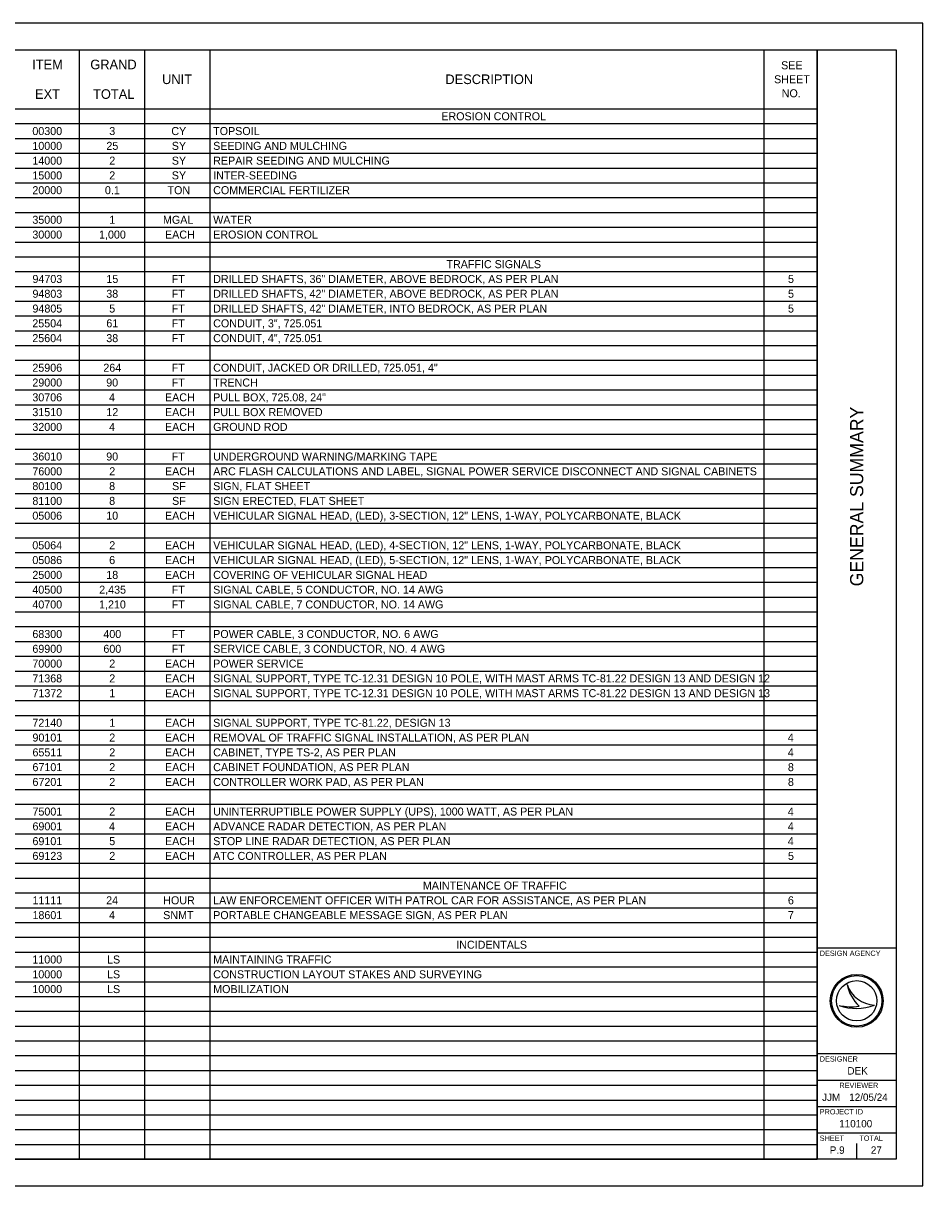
# Model space of a CAD drawing. Extents: x 0 to 34, y 0 to 22.
# Drawn here: x 16.98 to 34, y 0 to 22 of the extents above; entities that cross this region are included whole.
import ezdxf

# ---------------------------------------------------------------- set-up
doc = ezdxf.new("R2010")
doc.units = 0
for name, color, linetype in [('Default', 7, 'Continuous'), ('SH_Border', 7, 'Continuous'), ('SH_Cut_Line', 7, 'Continuous'), ('SH_Data', 7, 'Continuous')]:
    doc.layers.add(name, color=color, linetype=linetype)

msp = doc.modelspace()

# ---------------------------------------------------------------- linework, layer by layer
at = {"layer": 'Default'}
for p, q in [((1.5, 21.5), (32, 21.5)), ((18.035, 21.5), (18.035, 0.502)), ((19.27, 21.5), (19.27, 0.502)), ((20.505, 21.5), (20.505, 0.502)), ((30.995, 21.5), (30.995, 0.502)), ((32, 21.5), (32, 0.502)), ((1.5, 20.38), (32, 20.38)), ((1.5, 20.1), (32, 20.1)), ((1.5, 19.82), (32, 19.82)), ((1.5, 19.54), (32, 19.54)), ((1.5, 19.26), (32, 19.26)), ((1.5, 18.98), (32, 18.98)), ((1.5, 18.7), (32, 18.7)), ((1.5, 18.42), (32, 18.42)), ((1.5, 18.14), (32, 18.14)), ((1.5, 17.86), (32, 17.86)), ((1.5, 17.58), (32, 17.58)), ((1.5, 17.3), (32, 17.3)), ((1.5, 17.021), (32, 17.021)), ((1.5, 16.741), (32, 16.741)), ((1.5, 16.461), (32, 16.461)), ((1.5, 16.181), (32, 16.181)), ((1.5, 15.901), (32, 15.901)), ((1.5, 15.621), (32, 15.621)), ((1.5, 15.341), (32, 15.341)), ((1.5, 15.061), (32, 15.061)), ((1.5, 14.781), (32, 14.781)), ((1.5, 14.501), (32, 14.501)), ((1.5, 14.221), (32, 14.221)), ((1.5, 13.941), (32, 13.941)), ((1.5, 13.661), (32, 13.661)), ((1.5, 13.381), (32, 13.381)), ((1.5, 13.101), (32, 13.101)), ((1.5, 12.821), (32, 12.821)), ((1.5, 12.541), (32, 12.541)), ((1.5, 12.261), (32, 12.261)), ((1.5, 11.981), (32, 11.981)), ((1.5, 11.701), (32, 11.701)), ((1.5, 11.421), (32, 11.421)), ((1.5, 11.141), (32, 11.141)), ((1.5, 10.861), (32, 10.861)), ((1.5, 10.581), (32, 10.581)), ((1.5, 10.301), (32, 10.301)), ((1.5, 10.021), (32, 10.021)), ((1.5, 9.741), (32, 9.741)), ((1.5, 9.461), (32, 9.461)), ((1.5, 9.181), (32, 9.181)), ((1.5, 8.901), (32, 8.901)), ((1.5, 8.621), (32, 8.621)), ((1.5, 8.342), (32, 8.342)), ((1.5, 8.062), (32, 8.062)), ((1.5, 7.782), (32, 7.782)), ((1.5, 7.502), (32, 7.502)), ((1.5, 7.222), (32, 7.222)), ((1.5, 6.942), (32, 6.942)), ((1.5, 6.662), (32, 6.662)), ((1.5, 6.382), (32, 6.382)), ((1.5, 6.102), (32, 6.102)), ((1.5, 5.822), (32, 5.822)), ((1.5, 5.542), (32, 5.542)), ((1.5, 5.262), (32, 5.262)), ((1.5, 4.982), (32, 4.982)), ((1.5, 4.702), (32, 4.702)), ((1.5, 4.422), (32, 4.422)), ((1.5, 4.142), (32, 4.142)), ((1.5, 3.862), (32, 3.862)), ((1.5, 3.582), (32, 3.582)), ((1.5, 3.302), (32, 3.302)), ((1.5, 3.022), (32, 3.022)), ((1.5, 2.742), (32, 2.742)), ((1.5, 2.462), (32, 2.462)), ((1.5, 2.182), (32, 2.182)), ((1.5, 1.902), (32, 1.902)), ((1.5, 1.622), (32, 1.622)), ((1.5, 1.342), (32, 1.342)), ((1.5, 1.062), (32, 1.062)), ((1.5, 0.782), (32, 0.782)), ((1.5, 0.502), (32, 0.502))]:
    msp.add_line(p, q, dxfattribs=at)
at = {"layer": 'SH_Border'}
for p, q in [((32, 0.5), (32, 21.5)), ((32, 4.5), (33.5, 4.5)), ((32, 2.5), (33.5, 2.5)), ((32, 2), (33.5, 2)), ((32, 1.5), (33.5, 1.5)), ((32, 1), (33.5, 1))]:
    msp.add_line(p, q, dxfattribs=at)
msp.add_lwpolyline([(1.5, 21.5), (33.5, 21.5), (33.5, 0.5), (1.5, 0.5)], close=True, dxfattribs=at)
at = {"layer": 'SH_Cut_Line'}
msp.add_lwpolyline([(0, 0), (34, 0), (34, 22), (0, 22)], close=True, dxfattribs=at)
at = {"layer": 'SH_Data'}
for p, q in [((32.567, 3.81), (32.567, 3.81)), ((32.417, 3.41), (32.417, 3.41)), ((32.75, 3.5), (32.75, 3.5)), ((33.087, 3.419), (33.087, 3.419)), ((32.375, 0.675), (32.375, 0.675)), ((32.75, 0.5), (32.75, 0.8))]:
    msp.add_line(p, q, dxfattribs=at)
for radius in [0.5, 0.477, 0.477, 0.382]:
    msp.add_circle((32.75, 3.5), radius, dxfattribs=at)
for centre, radius, start, end in [((33.116, 3.998), 0.58, 198.9257, 198.9319), ((33.347, 3.97), 0.796, 191.6379, 191.6421), ((33.116, 3.998), 0.58, 198.9319, 267.1657), ((33.347, 3.97), 0.796, 191.6421, 226.0947), ((32.739, 4.37), 1.013, 251.4576, 290.0832), ((32.648, 4.654), 1.266, 259.4964, 259.4995), ((32.739, 4.37), 1.013, 251.4527, 251.4576), ((32.648, 4.654), 1.266, 259.4995, 276.6672)]:
    msp.add_arc(centre, radius, start, end, dxfattribs=at)

# ---------------------------------------------------------------- texts
at = {"layer": 'Default'}
for s, height, p in [('ITEM', 0.1818, (17.145, 21.129)), ('GRAND', 0.1818, (18.245, 21.129)), ('SEE ', 0.1515, (31.32, 21.129)), ('UNIT', 0.1818, (19.604, 20.849)), ('DESCRIPTION', 0.18181, (24.965, 20.849)), ('SHEET ', 0.1515, (31.187, 20.864)), ('EXT', 0.1818, (17.199, 20.569)), ('TOTAL', 0.1818, (18.297, 20.569)), ('NO.', 0.1515, (31.331, 20.599)), ('EROSION CONTROL', 0.15151, (24.889, 20.164)), ('00300', 0.1515, (17.149, 19.884)), ('3', 0.152, (18.604, 19.884)), ('CY', 0.1515, (19.779, 19.884)), ('TOPSOIL', 0.1515, (20.571, 19.884)), ('10000', 0.1515, (17.149, 19.604)), ('25', 0.1515, (18.55, 19.604)), ('SY', 0.1515, (19.788, 19.604)), ('SEEDING AND MULCHING', 0.15151, (20.571, 19.604)), ('14000', 0.1515, (17.149, 19.324)), ('2', 0.152, (18.604, 19.324)), ('SY', 0.1515, (19.788, 19.324)), ('REPAIR SEEDING AND MULCHING', 0.15151, (20.571, 19.324)), ('15000', 0.1515, (17.149, 19.045)), ('2', 0.152, (18.604, 19.045)), ('SY', 0.1515, (19.788, 19.045)), ('INTER-SEEDING', 0.15151, (20.571, 19.045)), ('20000', 0.1515, (17.149, 18.765)), ('0.1', 0.1515, (18.522, 18.765)), ('TON', 0.1515, (19.707, 18.765)), ('COMMERCIAL FERTILIZER', 0.15151, (20.571, 18.765)), ('35000', 0.1515, (17.149, 18.205)), ('1', 0.152, (18.604, 18.205)), ('MGAL', 0.1515, (19.621, 18.205)), ('WATER', 0.1515, (20.571, 18.205)), ('30000', 0.1515, (17.149, 17.925)), ('1,000', 0.1515, (18.411, 17.925)), ('EACH', 0.1515, (19.659, 17.925)), ('EROSION CONTROL', 0.15151, (20.571, 17.925)), ('TRAFFIC SIGNALS', 0.15151, (24.986, 17.365)), ('94703', 0.1515, (17.151, 17.085)), ('15', 0.1515, (18.55, 17.085)), ('FT', 0.1515, (19.786, 17.085)), ('DRILLED SHAFTS, 36" DIAMETER, ABOVE BEDROCK, AS PER PLAN', 0.15151, (20.571, 17.085)), ('5', 0.152, (31.45, 17.085)), ('94803', 0.1515, (17.151, 16.805)), ('38', 0.1515, (18.548, 16.805)), ('FT', 0.1515, (19.786, 16.805)), ('DRILLED SHAFTS, 42" DIAMETER, ABOVE BEDROCK, AS PER PLAN', 0.15151, (20.571, 16.805)), ('5', 0.152, (31.45, 16.805)), ('94805', 0.1515, (17.151, 16.525)), ('5', 0.152, (18.604, 16.525)), ('FT', 0.1515, (19.786, 16.525)), ('DRILLED SHAFTS, 42" DIAMETER, INTO BEDROCK, AS PER PLAN', 0.15151, (20.571, 16.525)), ('5', 0.152, (31.45, 16.525)), ('25504', 0.1515, (17.148, 16.245)), ('61', 0.1515, (18.549, 16.245)), ('FT', 0.1515, (19.786, 16.245)), ('CONDUIT, 3", 725.051', 0.15151, (20.571, 16.245)), ('25604', 0.1515, (17.148, 15.965)), ('38', 0.1515, (18.548, 15.965)), ('FT', 0.1515, (19.786, 15.965)), ('CONDUIT, 4", 725.051', 0.15151, (20.571, 15.965)), ('25906', 0.1515, (17.149, 15.405)), ('264', 0.1515, (18.492, 15.405)), ('FT', 0.1515, (19.786, 15.405)), ('CONDUIT, JACKED OR DRILLED, 725.051, 4"', 0.15151, (20.571, 15.405)), ('29000', 0.1515, (17.149, 15.125)), ('90', 0.1515, (18.547, 15.125)), ('FT', 0.1515, (19.786, 15.125)), ('TRENCH', 0.1515, (20.571, 15.125)), ('30706', 0.1515, (17.149, 14.845)), ('4', 0.152, (18.601, 14.845)), ('EACH', 0.1515, (19.659, 14.845)), ('PULL BOX, 725.08, 24"', 0.15151, (20.571, 14.845)), ('31510', 0.1515, (17.149, 14.565)), ('12', 0.1515, (18.549, 14.565)), ('EACH', 0.1515, (19.659, 14.565)), ('PULL BOX REMOVED', 0.15151, (20.571, 14.565)), ('32000', 0.1515, (17.149, 14.285)), ('4', 0.152, (18.601, 14.285)), ('EACH', 0.1515, (19.659, 14.285)), ('GROUND ROD', 0.1515, (20.571, 14.285)), ('36010', 0.1515, (17.149, 13.725)), ('90', 0.1515, (18.547, 13.725)), ('FT', 0.1515, (19.786, 13.725)), ('UNDERGROUND WARNING/MARKING TAPE', 0.15151, (20.571, 13.725)), ('76000', 0.1515, (17.149, 13.445)), ('2', 0.152, (18.604, 13.445)), ('EACH', 0.1515, (19.659, 13.445)), ('ARC FLASH CALCULATIONS AND LABEL, SIGNAL POWER SERVICE DISCONNECT AND SIGNAL CABINETS', 0.15151, (20.571, 13.445)), ('80100', 0.1515, (17.149, 13.165)), ('8', 0.152, (18.602, 13.165)), ('SF', 0.1515, (19.793, 13.165)), ('SIGN, FLAT SHEET', 0.15151, (20.571, 13.165)), ('81100', 0.1515, (17.149, 12.885)), ('8', 0.152, (18.602, 12.885)), ('SF', 0.1515, (19.793, 12.885)), ('SIGN ERECTED, FLAT SHEET', 0.15151, (20.571, 12.885)), ('VEHICULAR SIGNAL HEAD, (LED), 3-SECTION, 12" LENS, 1-WAY, POLYCARBONATE, BLACK', 0.15151, (20.571, 12.605)), ('05006', 0.1515, (17.149, 12.605)), ('10', 0.1515, (18.547, 12.605)), ('EACH', 0.1515, (19.659, 12.605)), ('05064', 0.1515, (17.148, 12.045)), ('2', 0.152, (18.604, 12.045)), ('EACH', 0.1515, (19.659, 12.045)), ('VEHICULAR SIGNAL HEAD, (LED), 4-SECTION, 12" LENS, 1-WAY, POLYCARBONATE, BLACK', 0.15151, (20.571, 12.045)), ('05086', 0.1515, (17.149, 11.765)), ('6', 0.152, (18.602, 11.765)), ('EACH', 0.1515, (19.659, 11.765)), ('VEHICULAR SIGNAL HEAD, (LED), 5-SECTION, 12" LENS, 1-WAY, POLYCARBONATE, BLACK', 0.15151, (20.571, 11.765)), ('25000', 0.1515, (17.149, 11.485)), ('18', 0.1515, (18.548, 11.485)), ('EACH', 0.1515, (19.659, 11.485)), ('COVERING OF VEHICULAR SIGNAL HEAD', 0.15151, (20.571, 11.485)), ('40500', 0.1515, (17.149, 11.205)), ('2,435', 0.1515, (18.414, 11.205)), ('FT', 0.1515, (19.786, 11.205)), ('SIGNAL CABLE, 5 CONDUCTOR, NO. 14 AWG', 0.15151, (20.571, 11.205)), ('40700', 0.1515, (17.149, 10.925)), ('1,210', 0.1515, (18.411, 10.925)), ('FT', 0.1515, (19.786, 10.925)), ('SIGNAL CABLE, 7 CONDUCTOR, NO. 14 AWG', 0.15151, (20.571, 10.925)), ('68300', 0.1515, (17.149, 10.366)), ('400', 0.1515, (18.493, 10.366)), ('FT', 0.1515, (19.786, 10.366)), ('POWER CABLE, 3 CONDUCTOR, NO. 6 AWG', 0.15151, (20.571, 10.366)), ('69900', 0.1515, (17.149, 10.086)), ('600', 0.1515, (18.493, 10.086)), ('FT', 0.1515, (19.786, 10.086)), ('SERVICE CABLE, 3 CONDUCTOR, NO. 4 AWG', 0.15151, (20.571, 10.086)), ('70000', 0.1515, (17.149, 9.806)), ('2', 0.152, (18.604, 9.806)), ('EACH', 0.1515, (19.659, 9.806)), ('POWER SERVICE', 0.15151, (20.571, 9.806)), ('71368', 0.1515, (17.149, 9.526)), ('2', 0.152, (18.604, 9.526)), ('EACH', 0.1515, (19.659, 9.526)), ('SIGNAL SUPPORT, TYPE TC-12.31 DESIGN 10 POLE, WITH MAST ARMS TC-81.22 DESIGN 13 AND DESIGN 12', 0.15151, (20.571, 9.526)), ('71372', 0.1515, (17.151, 9.246)), ('1', 0.152, (18.604, 9.246)), ('EACH', 0.1515, (19.659, 9.246)), ('SIGNAL SUPPORT, TYPE TC-12.31 DESIGN 10 POLE, WITH MAST ARMS TC-81.22 DESIGN 13 AND DESIGN 13', 0.15151, (20.571, 9.246)), ('72140', 0.1515, (17.149, 8.686)), ('1', 0.152, (18.604, 8.686)), ('EACH', 0.1515, (19.659, 8.686)), ('SIGNAL SUPPORT, TYPE TC-81.22, DESIGN 13', 0.15151, (20.571, 8.686)), ('90101', 0.1515, (17.151, 8.406)), ('2', 0.152, (18.604, 8.406)), ('EACH', 0.1515, (19.659, 8.406)), ('REMOVAL OF TRAFFIC SIGNAL INSTALLATION, AS PER PLAN', 0.15151, (20.571, 8.406)), ('4', 0.152, (31.446, 8.406)), ('65511', 0.1515, (17.151, 8.126)), ('2', 0.152, (18.604, 8.126)), ('EACH', 0.1515, (19.659, 8.126)), ('CABINET, TYPE TS-2, AS PER PLAN', 0.15151, (20.571, 8.126)), ('4', 0.152, (31.446, 8.126)), ('67101', 0.1515, (17.151, 7.846)), ('2', 0.152, (18.604, 7.846)), ('EACH', 0.1515, (19.659, 7.846)), ('CABINET FOUNDATION, AS PER PLAN', 0.15151, (20.571, 7.846)), ('8', 0.152, (31.448, 7.846)), ('67201', 0.1515, (17.151, 7.566)), ('2', 0.152, (18.604, 7.566)), ('EACH', 0.1515, (19.659, 7.566)), ('CONTROLLER WORK PAD, AS PER PLAN', 0.15151, (20.571, 7.566)), ('8', 0.152, (31.448, 7.566)), ('75001', 0.1515, (17.151, 7.006)), ('2', 0.152, (18.604, 7.006)), ('EACH', 0.1515, (19.659, 7.006)), ('UNINTERRUPTIBLE POWER SUPPLY (UPS), 1000 WATT, AS PER PLAN', 0.15151, (20.571, 7.006)), ('4', 0.152, (31.446, 7.006)), ('69001', 0.1515, (17.151, 6.726)), ('4', 0.152, (18.601, 6.726)), ('EACH', 0.1515, (19.659, 6.726)), ('ADVANCE RADAR DETECTION, AS PER PLAN', 0.15151, (20.571, 6.726)), ('4', 0.152, (31.446, 6.726)), ('69101', 0.1515, (17.151, 6.446)), ('5', 0.152, (18.604, 6.446)), ('EACH', 0.1515, (19.659, 6.446)), ('STOP LINE RADAR DETECTION, AS PER PLAN', 0.15151, (20.571, 6.446)), ('4', 0.152, (31.446, 6.446)), ('69123', 0.1515, (17.151, 6.166)), ('2', 0.152, (18.604, 6.166)), ('EACH', 0.1515, (19.659, 6.166)), ('ATC CONTROLLER, AS PER PLAN', 0.15151, (20.571, 6.166)), ('5', 0.152, (31.45, 6.166)), ('MAINTENANCE OF TRAFFIC', 0.15151, (24.539, 5.606)), ('11111', 0.1515, (17.151, 5.326)), ('24', 0.1515, (18.546, 5.326)), ('HOUR', 0.1515, (19.626, 5.326)), ('LAW ENFORCEMENT OFFICER WITH PATROL CAR FOR ASSISTANCE, AS PER PLAN', 0.15151, (20.571, 5.326)), ('6', 0.152, (31.448, 5.326)), ('18601', 0.1515, (17.151, 5.046)), ('4', 0.152, (18.601, 5.046)), ('SNMT', 0.1515, (19.625, 5.046)), ('PORTABLE CHANGEABLE MESSAGE SIGN, AS PER PLAN', 0.15151, (20.571, 5.046)), ('7', 0.152, (31.448, 5.046)), ('INCIDENTALS', 0.15151, (25.171, 4.486)), ('11000', 0.1515, (17.149, 4.206)), ('LS', 0.1515, (18.562, 4.206)), ('MAINTAINING TRAFFIC', 0.15151, (20.571, 4.206)), ('10000', 0.1515, (17.149, 3.926)), ('LS', 0.1515, (18.562, 3.926)), ('CONSTRUCTION LAYOUT STAKES AND SURVEYING', 0.15151, (20.571, 3.926)), ('10000', 0.1515, (17.149, 3.646)), ('LS', 0.1515, (18.562, 3.646)), ('MOBILIZATION', 0.15151, (20.571, 3.646))]:
    msp.add_text(s, height=height, dxfattribs=at).set_placement(p)
at = {"layer": 'SH_Data'}
msp.add_text('GENERAL SUMMARY', height=0.25, rotation=90, dxfattribs=at).set_placement((32.875, 11.344))
for s, height, p in [('DESIGN AGENCY', 0.1, (32.05, 4.35)), ('DESIGNER', 0.1, (32.05, 2.35)), ('DEK', 0.14, (32.574, 2.105)), ('REVIEWER', 0.1, (32.422, 1.85)), ('JJM', 0.14, (32.095, 1.605)), ('12/05/24', 0.14, (32.608, 1.605)), ('PROJECT ID', 0.1, (32.05, 1.35)), ('110100', 0.14, (32.419, 1.105)), ('SHEET', 0.1, (32.05, 0.85)), ('TOTAL', 0.1, (32.8, 0.85)), ('P.9', 0.14, (32.24, 0.605)), ('27', 0.14, (33.018, 0.605))]:
    msp.add_text(s, height=height, dxfattribs=at).set_placement(p)

doc.saveas('drawing.dxf')
